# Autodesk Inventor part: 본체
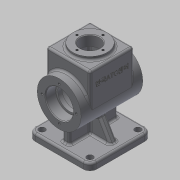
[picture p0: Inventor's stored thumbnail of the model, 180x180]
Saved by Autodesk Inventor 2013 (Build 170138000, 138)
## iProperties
Created: 2019-01
Part Number: 본체
Material: 알루미늄 6061
Document SubType Name: Modeling
Designer: mduedu
Density: 2.71 g/cm^3
Author: mduedu
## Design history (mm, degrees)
sketch "스케치1"
  geometry: C1 r 32 at (0, 0); 1 further point
  constraints: 1 centre point, 1 coincident
  dimensions: "d0" = 64 diameter of C1
extrude "돌출1" new body sketch "스케치1" stored distance "d1" = 90; taper "d2" = 0 deg
sketch "스케치2"
  geometry: L1 (0, 32)-(50, 32); L2 (50, 32)-(50, -32); L3 (50, -32)-(0, -32); L4 (0, -32)-(0, 32); C1 r 32 at (0, 0) reference; 2 further points
  constraints: 8 end point, 2 parallel, 1 coincident, 1 horizontal, 1 midpoint, 1 perpendicular, 1 tangent
  dimensions: "d5" = 50 distance between parallel lines of L4 L2
extrude "돌출2" join sketch "스케치2" stored distance "d7" = 64; taper "d8" = 0 deg
sketch "스케치3"
  geometry: C1 r 25 at (32, 32); 1 further point
  constraints: 1 centre point, 1 coincident
  dimensions: "d9" = 50 diameter of C1
extrude "돌출3" join sketch "스케치3" distance "d10" = 5; taper "d11" = 0 deg
sketch "스케치4"
  geometry: L1 (40, 25)-(0, 25); L2 (0, 25)-(0, -25); L3 (0, -25)-(40, -25); L4 (40, -25)-(40, 25); L5 (55, -25)-(55, 25) reference; A1 r 25 centre (0, 0) between (0, 25) and (0, -25); A2 r 25 centre (0, 0) between (0, -25) and (0, 25); 2 further points
  constraints: 8 end point, 4 point on circle, 2 centre point, 2 coincident, 2 parallel, 1 horizontal, 1 midpoint, 1 perpendicular, 1 tangent
  dimensions: "d12" = 50 diameter of A1; "d13" = 15 distance between parallel lines of L4 L5
extrude "돌출4" cut sketch "스케치4" stored distance "d14" = 48; taper "d15" = 0 deg
sketch "스케치5"
  geometry: C1 r 20 at (0, 0); 1 further point
  constraints: 1 centre point, 1 coincident
  dimensions: "d16" = 40 diameter of C1
extrude "돌출5" cut sketch "스케치5" distance "d17" = 15; taper "d18" = 0 deg
sketch "스케치6"
  geometry: C1 r 17 at (0, 0); 1 further point
  constraints: 1 centre point, 1 coincident
  dimensions: "d19" = 34 diameter of C1
extrude "돌출6" cut sketch "스케치6" stored distance "d20" = 15; taper "d21" = 0 deg
fillet "모깎기1" dims "d22" = 0.3
fillet "모깎기2" dims "d23" = 3
fillet "모깎기3" dims "d24" = 3
fillet "모깎기4" dims "d25" = 3
fillet "모깎기5" dims "d26" = 3
fillet "모깎기6" dims "d27" = 3
sketch "스케치7"
  geometry: C1 r 14 at (0, 0); 1 further point
  constraints: 1 centre point, 1 coincident
  dimensions: "d28" = 28 diameter of C1
extrude "돌출7" cut sketch "스케치7" stored distance "d29" = 15; taper "d30" = 0 deg
chamfer "모따기1" distance "d31" = 1; stored, may be unused: second distance "d32" = 2, angle "d33" = 45 deg
chamfer "모따기2" distance "d34" = 1; stored, may be unused: second distance "d35" = 2, angle "d36" = 45 deg
node "작업 평면1"
sketch "스케치8"
  geometry: L1 (45, -45)-(-45, -45); L2 (-45, -45)-(-45, 45); L3 (-45, 45)-(45, 45); L4 (45, 45)-(45, -45); 3 further points
  constraints: 8 end point, 2 midpoint, 2 parallel, 1 horizontal, 1 horizontal alignment, 1 perpendicular, 1 vertical alignment
  dimensions: "d39" = 90 distance of L1.start L1.end; "d40" = 90 distance of L1.end L2.end
extrude "돌출8" join sketch "스케치8" distance "d41" = 10; taper "d42" = 0 deg
sketch "스케치9"
  geometry: L1 (-35, 5)-(35, 5); L2 (35, 5)-(35, -5); L3 (35, -5)-(-35, -5); L4 (-35, -5)-(-35, 5); 3 further points
  constraints: 8 end point, 2 midpoint, 2 parallel, 1 horizontal, 1 horizontal alignment, 1 perpendicular, 1 vertical alignment
  dimensions: "d52" = 10 distance of L1.end L2.end; "d54" = 70 distance of L1.start L1.end
extrude "돌출9" join sketch "스케치9" stored distance "d50" = 10; taper "d51" = 0 deg
sketch "스케치10"
  geometry: L1 (0, -25)-(37, -25) reference; L2 (40, -22)-(40, -14) reference; L3 (40, -14)-(54, -14) reference; L4 (54, -14)-(55, -15) reference; L5 (55, -15)-(55, -25) reference; L6 (55, -25)-(53, -25) reference; L7 (50, -28)-(50, -29) reference; L8 (47, -32)-(0, -32) reference; L9 (-31.607, -5)-(-55, -5) reference; L10 (-55, -5)-(-55, -45) reference; L11 (-55, -45)-(-65, -45) reference; L12 (-65, -45)-(-65, 45) reference; L13 (-65, 45)-(-55, 45) reference; L14 (-55, 45)-(-55, 5) reference; L15 (-55, 5)-(-31.607, 5) reference; L16 (0, 32)-(47, 32) reference; L17 (50, 29)-(50, 28) reference; L18 (53, 25)-(55, 25) reference; L19 (55, 25)-(55, 15) reference; L20 (55, 15)-(54, 14) reference; L21 (54, 14)-(40, 14) reference; L22 (40, 14)-(40, 22) reference; L23 (37, 25)-(0, 25) reference; L24 (-55, 35)-(-26.2, 18.372); A1 r 25 centre (0, 0) between (0, 25) and (0, -25) reference; A2 r 3 centre (37, -22) between (37, -25) and (40, -22) reference; A3 r 3 centre (53, -28) between (53, -25) and (50, -28) reference; A4 r 3 centre (47, -29) between (47, -32) and (50, -29) reference; A5 r 32 centre (0, 0) between (-31.607, -5) and (0, -32) reference; A6 r 32 centre (0, 0) between (0, 32) and (-31.607, 5) reference; A7 r 3 centre (47, 29) between (50, 29) and (47, 32) reference; A8 r 3 centre (53, 28) between (50, 28) and (53, 25) reference; A9 r 3 centre (37, 22) between (40, 22) and (37, 25) reference; 1 further point
  constraints: 2 end point, 1 point on circle, 1 point on line
  dimensions: "d55" = 35 vertical distance of L24.start point (0, 0); "d56" = 120 deg angle of L24 L14
feature "리브1" sketch "스케치10" dims "d57" = 1, "d58" = 10, "d59" = 0, "d60" = 0, "d61" = 1, "d62" = 1
fillet "모깎기7" dims "d63" = 3
fillet "모깎기8" dims "d64" = 3
fillet "모깎기9" dims "d65" = 10
sketch "스케치11"
  geometry: L1 (-45, 35)-(-45, -35) reference; L2 (-35, -45)-(35, -45) reference; L3 (45, -35)-(45, 35) reference; L4 (35, 45)-(-35, 45) reference; L5 (8, -29.804)-(8, -8) reference; L6 (-2, -36.732)-(2, -36.732) reference; L7 (-8, -8)-(-8, -29.804) reference; L8 (-32, -8)-(-8, -8) reference; L9 (-38, 2)-(-38, -2) reference; L10 (-8, 8)-(-32, 8) reference; L11 (-8, 29.804)-(-8, 8) reference; L12 (2, 36.732)-(-2, 36.732) reference; L13 (8, 8)-(8, 29.804) reference; L14 (32, 8)-(8, 8) reference; L15 (38, -2)-(38, 2) reference; L16 (8, -8)-(32, -8) reference; A1 r 10 centre (-35, 35) between (-35, 45) and (-45, 35) reference; A2 r 10 centre (-35, -35) between (-45, -35) and (-35, -45) reference; A3 r 10 centre (35, -35) between (35, -45) and (45, -35) reference; A4 r 10 centre (35, 35) between (45, 35) and (35, 45) reference; A5 r 6 centre (-32, -2) between (-38, -2) and (-32, -8) reference; A6 r 6 centre (-32, 2) between (-32, 8) and (-38, 2) reference; A7 r 6 centre (32, 2) between (38, 2) and (32, 8) reference; A8 r 6 centre (32, -2) between (32, -8) and (38, -2) reference; 9 further points; 4 other entities
  constraints: 4 coincident, 4 other
hole "구멍1" sketch "스케치11" at (-35, 35), (35, 35), (35, -35), (-35, -35) diameter "d66" = 9; stored, may be unused: countersink angle "d70" = 90 deg, drill point angle "d72" = 118 deg; dims "d67" = 6, "d68" = 4, "d69" = 2, "d71" = 8
fillet "모깎기10" dims "d73" = 3
sketch "스케치12"
  geometry: L1 (-3, 47)-(-3, 19.596) reference; 2 further points
  constraints: 1 other
  dimensions: "d74" = 32 distance from line of point (29, 30) L1; "d75" = 30 distance of point (29, 30) point (29, 0)
feature "엠보싱1" sketch "스케치12" dims "d76" = 0.5, "d77" = 0
sketch "스케치13"
  geometry: 4 further points
  constraints: 4 other
hole "구멍2" sketch "스케치13" at (-25, 0), (0, -25), (25, 0), (0, 25) diameter "d78" = 3.242; stored, may be unused: countersink angle "d82" = 90 deg, drill point angle "d84" = 120 deg; dims "d79" = 7, "d80" = 4, "d81" = 2, "d83" = 9
sketch "스케치14"
  geometry: 4 further points
  constraints: 4 other
hole "구멍3" sketch "스케치14" at (-25, 0), (0, -25), (25, 0), (0, 25) diameter "d85" = 3.242; stored, may be unused: countersink angle "d89" = 90 deg, drill point angle "d91" = 120 deg; dims "d86" = 7, "d87" = 4, "d88" = 2, "d90" = 9
sketch "스케치15"
  geometry: 4 further points
  constraints: 4 other
hole "구멍4" sketch "스케치15" at (0, -19), (19, 0), (0, 19), (-19, 0) diameter "d92" = 3.242; stored, may be unused: countersink angle "d96" = 90 deg, drill point angle "d98" = 120 deg; dims "d93" = 8, "d94" = 4, "d95" = 2, "d97" = 10
node "솔리드1"
mirror "대칭1"
mirror "대칭2"
node "투영된 루프1"
node "절단 모서리 투영1"
node "절단 모서리 투영2"
other parameters: "d37" = -65
